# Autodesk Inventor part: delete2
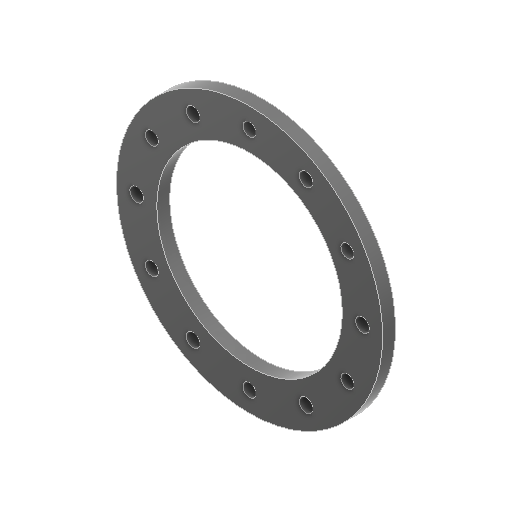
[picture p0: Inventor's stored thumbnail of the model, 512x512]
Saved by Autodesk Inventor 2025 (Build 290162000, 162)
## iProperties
Created: 2025-01
Part Number: delete2
Material: Thermoplastic Resin
Document SubType Name: Modeling
Designer: dansp
Density: 1.28 g/cm^3
Appearance: Smooth - Black
Mass: 13.2627 g
Surface Area: 75.5829 cm^2
Volume: 10.3615 cm^3
Author: dansp
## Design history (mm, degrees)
sketch "Sketch1"
  geometry: L1 (0, 57.75)-(0, -57.75) reference; L2 (-57.75, 0)-(57.75, 0) reference; C1 r 41.25 at (0, 0); C2 r 28.75 at (0, 0); 1 further point
  constraints: 2 centre point, 2 coincident
  dimensions: "d0" = 82.5 diameter of C1; "d1" = 12.5 radial gap between concentric circles of C1 C2
extrude "Extrusion1" new body sketch "Sketch1" distance "d2" = 4; taper "d3" = 0 deg
sketch "Sketch2"
  geometry: L1 (0, 57.75)-(0, -57.75) reference; 8 further points
  constraints: 3 point on line, 2 coincident, 2 vertical alignment, 2 other
  dimensions: "d157" = 12.5 distance of point (0, 41.25) point (0, 28.75) (derived); "d158" = 6.25 distance of point (0, 35) point (0, 28.75) (= 0.5 x d157)
hole "Hole1" sketch "Sketch2" at (0, 35) diameter "d5" = 4; stored, may be unused: countersink angle "d9" = 90 deg, drill point angle "d11" = 118 deg; dims "d6" = 12, "d7" = 4, "d8" = 2, "d10" = 8
pattern_circular "Circular Pattern2" dims angle "d18" = 360 deg
sketch "Sketch17"
  geometry: L1 (0, 0)-(-17.5, 30.311); L2 (0, -57.75)-(0, 57.75) reference; L3 (0, 0)-(20.74, -35.923); C1 r 2 at (-30.311, 17.5) reference; C2 r 2.1 at (-17.5, 30.311); C3 r 2.1 at (17.5, -30.311); A1 r 35 centre (0, 0) between (-30.311, 17.5) and (-17.5, 30.311); 1 further point
  constraints: 4 end point, 3 centre point, 3 point on circle, 1 coincident, 1 collinear, 1 point on line
  dimensions: "d148" = 4.2 diameter of C2; "d150" = 30 deg angle of L2 L1; "d151" = 4.2 diameter of C3 (= d148)
extrude "Extrusion3" cut sketch "Sketch17" extent not by distance; stored distance "d152" = 0; taper "d153" = 0 deg
pattern_circular "Circular Pattern3" dims angle "d155" = 360 deg
body "Solid1"
node "Projected Loop1"
other parameters: "d39" = 55 deg [user parameter], "Sketch3_Pitch" = 0.7 [user parameter], "d57" = 55 deg [user parameter], "Sketch5_Pitch" = 0.7 [user parameter], "d75" = 55 deg [user parameter], "Sketch7_Pitch" = 0.7 [user parameter], "d93" = 55 deg [user parameter], "Sketch9_Pitch" = 0.7 [user parameter], "d111" = 55 deg [user parameter], "Sketch11_Pitch" = 0.7 [user parameter], "d129" = 55 deg [user parameter], "Sketch13_Pitch" = 0.7 [user parameter]
